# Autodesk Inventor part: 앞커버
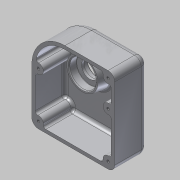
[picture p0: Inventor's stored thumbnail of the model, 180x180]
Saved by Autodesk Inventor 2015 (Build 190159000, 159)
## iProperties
Created: 2015-10
Part Number: 앞커버
Material: 알루미늄 6061
Document SubType Name: Modeling
Designer: mduedu
Density: 2.71 g/cm^3
Mass: 307.08 g
Surface Area: 494.818 cm^2
Volume: 113.314 cm^3
Appearance: 알루미늄 - 평지
Author: mduedu
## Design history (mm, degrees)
sketch "스케치1"
  geometry: L1 (0, 40)-(60, 40); L2 (60, 40)-(60, -63); L3 (60, -63)-(-40, -63); L4 (-40, -63)-(-40, 0); A1 r 40 centre (0, 0) between (0, 40) and (-40, 0); 1 further point
  constraints: 8 end point, 2 point on circle, 2 tangent, 1 centre point, 1 coincident, 1 horizontal, 1 parallel, 1 perpendicular, 1 vertical
  dimensions: "d0" = 40 radius of A1; "d1" = 103 distance of L1.end L2.end; "d2" = 100 distance of L2.end L3.end
extrude "돌출2" new body sketch "스케치1" distance "d8" = 40; taper "d9" = 0 deg
fillet "모깎기3" dims "d10" = 8
fillet "모깎기4" dims "d11" = 8
feature "쉘2" dims "d12" = 4
sketch "스케치2"
  geometry: C1 r 21.5 at (32, 55); 1 further point
  constraints: 1 centre point, 1 coincident
  dimensions: "d13" = 43 diameter of C1
extrude "돌출3" join sketch "스케치2" distance "d14" = 15; taper "d15" = 0 deg
hole "구멍1" diameter "d18" = 32; stored, may be unused: countersink angle "d22" = 90 deg, drill point angle "d24" = 0 deg; dims "d16" = 10, "d17" = 10, "d19" = 6, "d20" = 4, "d21" = 2, "d23" = 9
hole "구멍2" diameter "d27" = 20; stored, may be unused: countersink angle "d31" = 90 deg, drill point angle "d33" = 0 deg; dims "d25" = 10, "d26" = 10, "d28" = 6, "d29" = 4, "d30" = 2, "d32" = 3
hole "구멍3" diameter "d36" = 25; stored, may be unused: countersink angle "d40" = 90 deg, drill point angle "d42" = 0 deg; dims "d34" = 10, "d35" = 10, "d37" = 6, "d38" = 4, "d39" = 2, "d41" = 3
chamfer "모따기1" distance "d43" = 1; stored, may be unused: second distance "d44" = 2, angle "d45" = 45 deg
feature "면 기울기1" dims angle "d46" = 10 deg
sketch "스케치3"
  geometry: L1 (-40, 0)-(-40, -55) reference; L2 (60, -55)-(60, 32) reference; L3 (-40, 0)-(60, 0); C1 r 6 at (52, 32); C2 r 6 at (52, -55); C3 r 6 at (-32, -55); C4 r 6 at (52, 0); C5 r 6 at (-32, 0); A1 r 8 centre (52, 32) between (60, 32) and (52, 40) reference; A2 r 8 centre (52, -55) between (52, -63) and (60, -55) reference; A3 r 8 centre (-32, -55) between (-40, -55) and (-32, -63) reference; 1 further point
  constraints: 5 centre point, 4 equal radius, 3 coincident, 3 point on line, 2 end point, 2 vertical alignment, 1 perpendicular
  dimensions: "d47" = 6 radius of C1
extrude "돌출4" join sketch "스케치3" stored distance "d49" = 15; taper "d50" = 0 deg
fillet "모깎기5" dims "d51" = 3
fillet "모깎기6" dims "d52" = 3
sketch "스케치4"
  geometry: A1 r 6 centre (-32, 0) between (-32.667, -5.963) and (-31.833, 5.998) reference; A2 r 6 centre (52, 32) between (46.037, 32.667) and (52.667, 26.037) reference; A3 r 6 centre (52, 0) between (52.667, 5.963) and (52.667, -5.963) reference; A4 r 6 centre (52, -55) between (52.667, -49.037) and (46.037, -55.667) reference; A5 r 6 centre (-32, -55) between (-26.037, -55.667) and (-32.667, -49.037) reference; 6 further points
  constraints: 5 coincident
hole "구멍4" sketch "스케치4" at (-32, 0), (52, 32), (52, 0), (52, -55), (-32, -55) diameter "d53" = 3.242; stored, may be unused: countersink angle "d57" = 90 deg, drill point angle "d59" = 118 deg; dims "d54" = 12, "d55" = 4, "d56" = 2, "d58" = 14
sketch "스케치5"
  geometry: L1 (-52, -63)-(32, -63) reference; L2 (-60, 32)-(-60, -55) reference; 2 further points
  constraints: 1 other
  dimensions: "d60" = 20 distance from line of point (-10, -43) L1; "d61" = 50 distance from line of point (-10, -43) L2
feature "엠보싱1" sketch "스케치5" dims "d13" = 43, "d62" = 0.5, "d63" = 0
fillet "모깎기7" dims "d64" = 0.3
node "솔리드2"
